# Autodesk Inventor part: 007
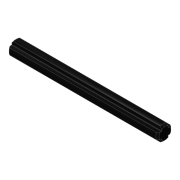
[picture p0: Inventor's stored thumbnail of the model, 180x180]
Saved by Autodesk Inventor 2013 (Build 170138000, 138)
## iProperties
Created: 2013-02
Part Number: 007
Material: Generic
Document SubType Name: Modeling
Designer: perblt
Density: 1 g/cm^3
Author: perblt
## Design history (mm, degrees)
sketch "Sketch1"
  geometry: L1 (1, -2.182)-(-1, -2.182); L2 (-1, 2.182)-(1, 2.182); L3 (1, -2.182)-(-1, 2.182); L4 (-1, -2.182)-(1, 2.182); L5 (-2.182, -1)-(-2.182, 1); L6 (2.182, 1)-(2.182, -1); L7 (2.182, -1)-(-2.182, 1); L8 (-2.182, -1)-(2.182, 1); L9 (2.182, -1)-(1, -1); L10 (-1, -1)-(-2.182, -1); L11 (1, 2.182)-(1, 1); L12 (1, -1)-(1, -2.182); L13 (-2.182, 1)-(-1, 1); L14 (1, 1)-(2.182, 1); L15 (-1, -2.182)-(-1, -1); L16 (-1, 1)-(-1, 2.182); A1 r 2.4 centre (0, 0) between (-1, -2.182) and (1, -2.182); A2 r 2.4 centre (0, 0) between (2.182, -1) and (2.182, 1); A3 r 2.4 centre (0, 0) between (1, 2.182) and (-1, 2.182); A4 r 2.4 centre (0, 0) between (-2.182, 1) and (-2.182, -1); 1 further point
  constraints: 32 end point, 10 parallel, 8 point on circle, 4 centre point, 4 midpoint, 4 perpendicular, 3 horizontal, 1 coincident
  dimensions: "d1" = 2 distance of L2.start L2.end; "d2" = 2 distance of L5.start L5.end
extrude "Extrusion1" new body sketch "Sketch1" distance "d3" = 48; taper "d4" = 0 deg
chamfer "Chamfer1" distance "d5" = 0.5; stored, may be unused: second distance "d6" = 2, angle "d7" = 45 deg
chamfer "Chamfer2" distance "d8" = 0.5; stored, may be unused: second distance "d9" = 2, angle "d10" = 45 deg
chamfer "Chamfer3" distance "d11" = 0.1; stored, may be unused: second distance "d12" = 2, angle "d13" = 45 deg
body "Solid1"
other parameters: "d0" = 4.8
